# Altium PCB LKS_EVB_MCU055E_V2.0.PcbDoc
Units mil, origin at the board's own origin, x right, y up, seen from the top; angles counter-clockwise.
Board outline 1880 x 1270 mil, 2 copper layers (Top Layer, Bottom Layer); 19 components, 27 nets, 78 pads, 29 vias.
Unrouted connection lines stored in the file: 1.
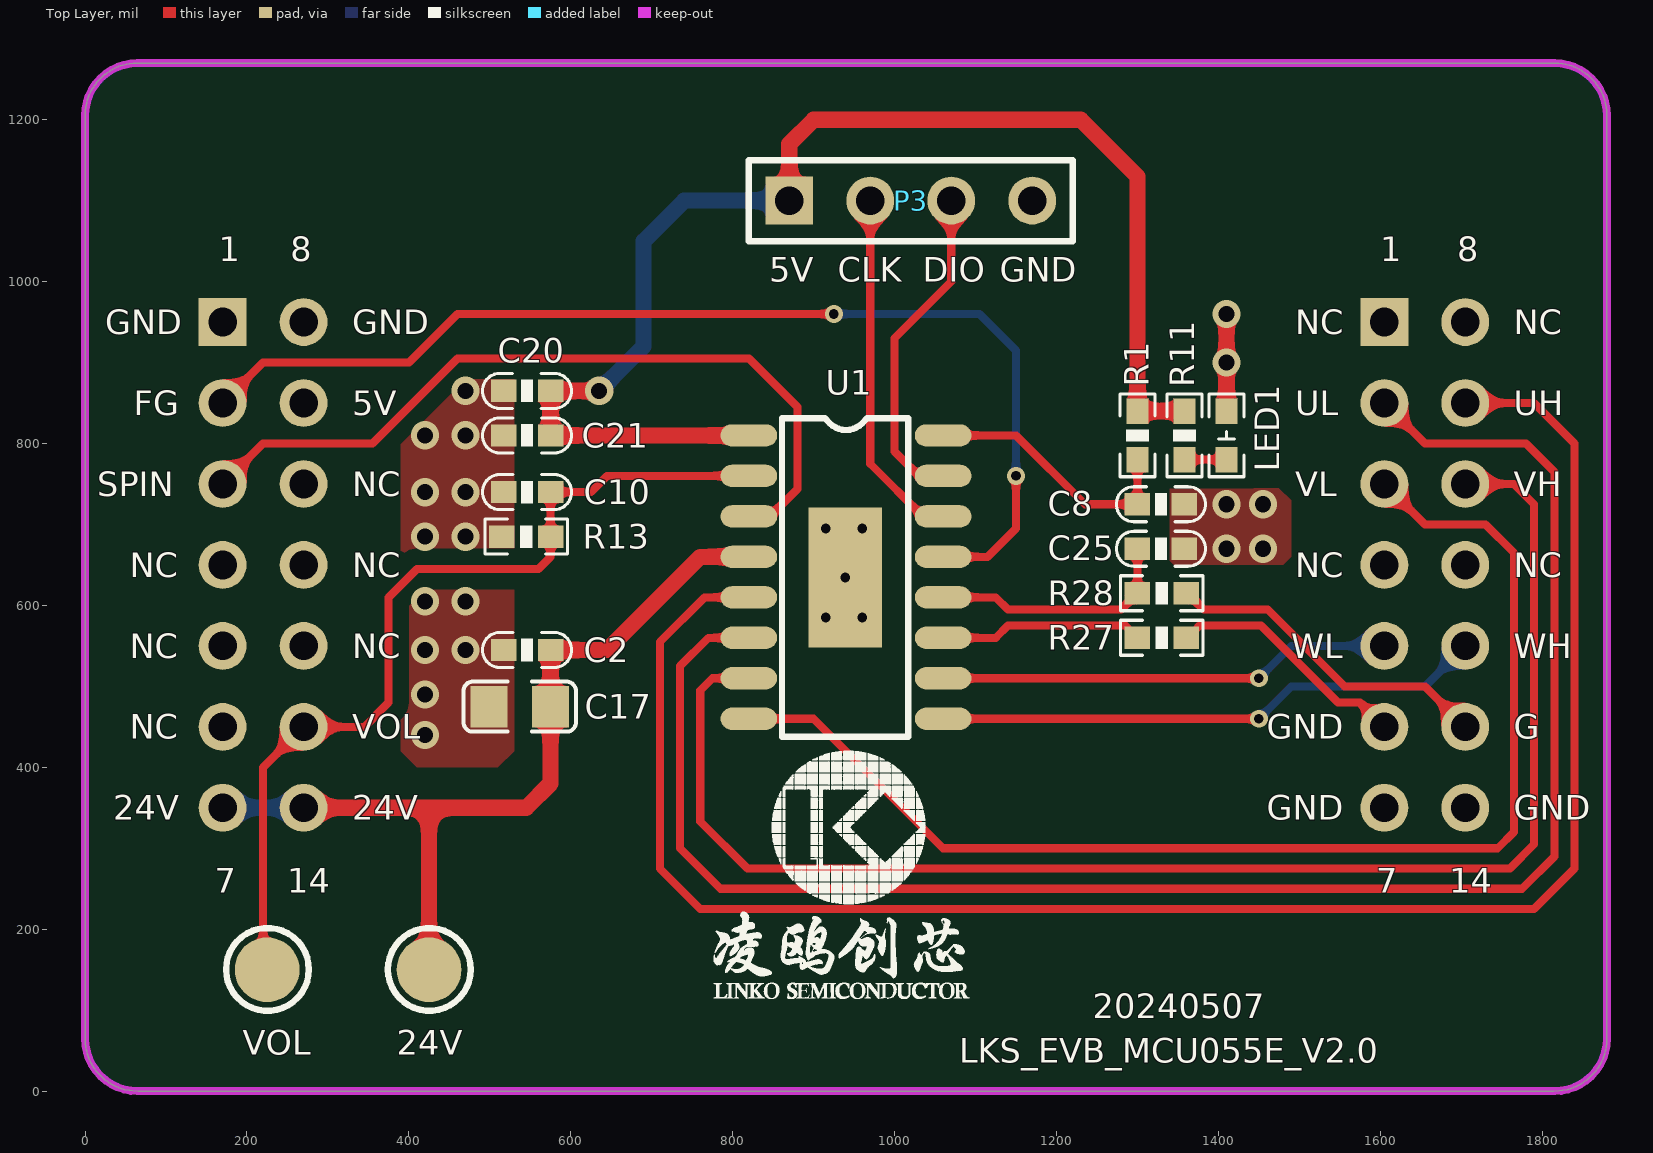
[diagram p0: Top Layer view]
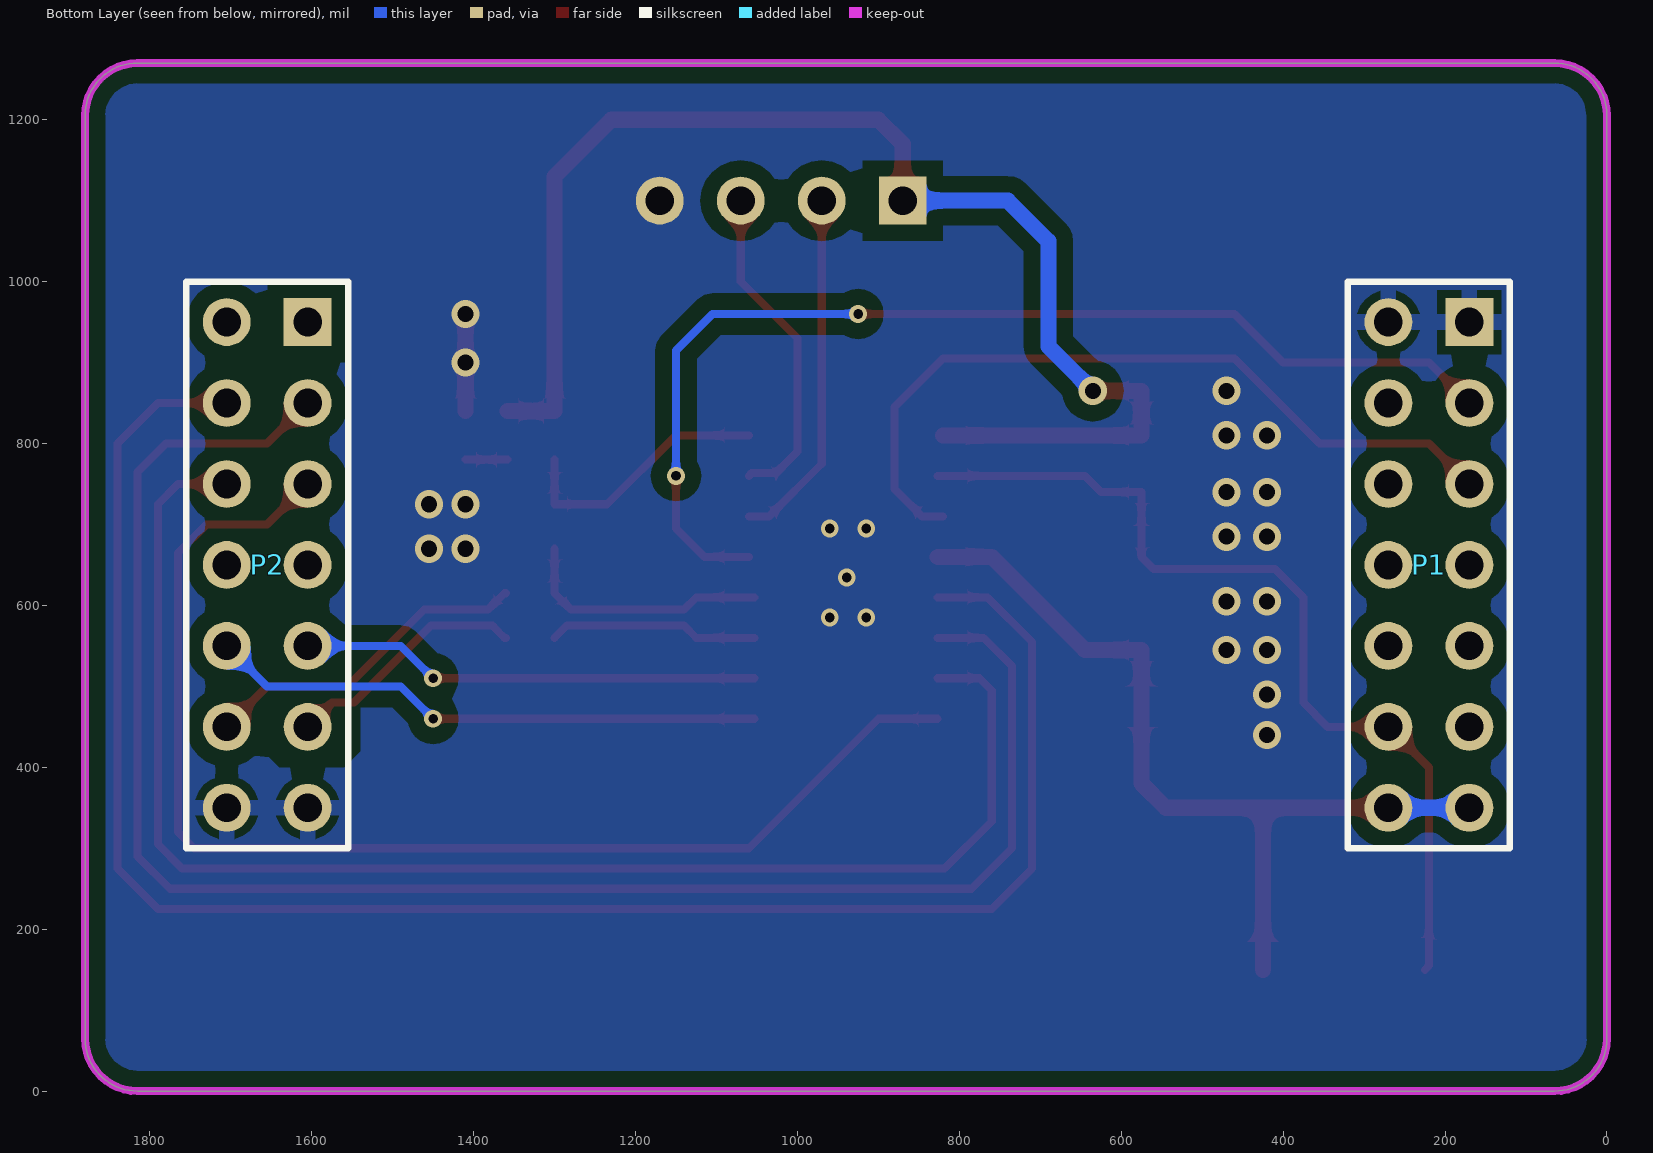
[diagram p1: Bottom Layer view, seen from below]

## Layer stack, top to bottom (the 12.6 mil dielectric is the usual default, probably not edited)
Top Solder: solder mask 0.4, Solder Resist, Dk 3.5
Top Layer: signal copper 1.4
Dielectric1: dielectric 12.6, FR-4, Dk 4.8
Bottom Layer: signal copper 1.4
Bottom Solder: solder mask 0.4, Solder Resist, Dk 3.5

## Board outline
0,65 0,1205 cw(c65,1205) 65,1270 1815,1270 cw(c1815,1205) 1880,1205 1880,65 cw(c1815,65) 1815,0 65,0 cw(c65,65)

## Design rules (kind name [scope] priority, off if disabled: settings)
Clearance Clearance_1 [INPolygon] p1: gap=20 ignorepadtopadclearanceinfootprint=FALSE except(0: Arc-Hole Track-Hole SMDPad-Hole THPad-Hole Via-Hole Fill-Hole Poly-Hole Region-Hole Text-Hole)
Clearance [All] p2: gap=10 ignorepadtopadclearanceinfootprint=FALSE except(0: Arc-Hole Track-Hole SMDPad-Hole THPad-Hole Via-Hole Fill-Hole Poly-Hole Region-Hole Text-Hole)
ComponentClearance [All] p1: gap=0 collisioncheckmode=3 verticalgap=0 showdistances=FALSE
FabricationTestpoint [(IsPad And (OnTopLayer Or OnBottomLayer))] p1: side=3 testpointundercomponent=TRUE minsize=40 maxsize=100 preferedsize=60 minholesize=0 maxholesize=40 preferedholesize=32 testpointgrid=1 allowsidetop=TRUE allowsidebottom=TRUE usegrid=TRUE gridtolerance=0.01
PolygonConnect PolygonConnect_1 [HasFootprint('HDR2X7_CEN') vs InNet('GND')] p1: connectstyle=Relief reliefconductorwidth=20 reliefentries=4 polygonreliefangle="90 Angle" airgapwidth=10
PolygonConnect [All] p2: connectstyle=Direct reliefconductorwidth=20 reliefentries=4 polygonreliefangle="90 Angle" airgapwidth=10
RoutingVias [All] p1: holewidth=12 width=20 viastyle="Through Hole" minholewidth=0 minwidth=10 maxholewidth=30 maxwidth=50
SilkToSolderMaskClearance SilkscreenOverComponentPads [IsPad] p1: minsilkscreentomaskgap=10 clearancetoexposedcopper=TRUE
SolderMaskExpansion [All] p1: expansion=4 istentingtop=FALSE
Width [All] p1: maxlimit=300 minlimit=1 preferedwidth=10
27 further rules are at their usual default settings.

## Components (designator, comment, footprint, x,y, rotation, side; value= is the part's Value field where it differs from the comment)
24V "TestP" TP-80 425.39,150.39 r90 top
C2 "100nF/50V" 0603C 546,545 r180 top
C8 "100nF/50V" 0603C 1329,725 r0 top
C10 "100nF/50V" 0603C 546,740 r180 top
C17 "10uF/50V" 0805C 537,475 r0 top
C20 "10uF/16V" 0603C 545.95,865 r0 top
C21 "100nF/50V" 0603C 546,810 r180 top
C25 "100pF/50V" 0603C 1329.06,670 r180 top
LED1 "" "LED 0603R" 1410,810 r90 top
P1 "Header 7X2A" HDR2X7_CEN 170,950 r270 bottom locked
P2 "Header 7X2A" HDR2X7_CEN 1605,950 r270 bottom locked
P3 "SWD" "HDR 1X4" 870,1100 r0 top
R1 "20K" 0603R 1300,810 r270 top
R11 "3.3K" 0603R 1358.06,810 r90 top
R13 "3.3K" 0603R 545,685 r180 top
R27 "1K" 0603R 1330,560 r0 top
R28 "1K" 0603R 1330,615 r0 top
U1 "LKS32MC055EL6S8" ESOP16 940,635 r0 top locked
VOL "TestP" TP-80 225.39,150.39 r90 top

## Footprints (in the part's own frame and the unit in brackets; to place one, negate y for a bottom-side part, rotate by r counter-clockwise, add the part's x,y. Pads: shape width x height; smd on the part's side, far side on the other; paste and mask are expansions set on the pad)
0603C [mm] "电容"
  rect 0.8x0.7 smd: 1(-0.737,0) 2(0.738,0)
  silkscreen extent -1.4,-0.55 1.4,0.55, body extent -0.8,-0.41 0.8,0.41, height 0.81
0603R [mm] "电阻"
  rect 0.8x0.7 smd: 1(-0.762,0) 2(0.762,0)
  silkscreen extent -1.3,-0.55 1.3,0.55, body extent -0.8,-0.4 0.8,0.4, height 0.45
0805C [mil] "电容"
  rect 46x51.18 smd: 1(-38,0) 2(38,0)
  silkscreen extent -69,-31 70,31, body extent -39,-24 39,24, height 20
ESOP16 [mil]
  round 15.75 on Top Overlay: 0(-48,167)
  rect 90.55x173.23 smd: 0(-1,-0.5)
  oval 70x27.56 smd: 1(-120,175) 2(-120,125) 3(-120,75) 4(-120,25) 5(-120,-25) 6(-120,-75) 7(-120,-125) 8(-120,-175) 9(120,-175) 10(120,-125) 11(120,-75) 12(120,-25) 13(120,25) 14(120,75) 15(120,125) 16(120,175)
  silkscreen extent -79,-197 77,196, body extent -119,-197 117,196, height 75
HDR2X7_CEN [mm] "Connector; Header; 7x2 Position"
  rect 1.5x1.5 hole 0.9: 1(0,0)
  round 1.5 hole 0.9: 2(2.54,0) 3(5.08,0) 4(7.62,0) 5(10.16,0) 6(12.7,0) 7(15.24,0) 8(0,-2.54) 9(2.54,-2.54) 10(5.08,-2.54) 11(7.62,-2.54) 12(10.16,-2.54) 13(12.7,-2.54) 14(15.24,-2.54)
  silkscreen extent -1.27,-3.81 16.51,1.27
"HDR 1X4" [mm] "单排针 2.54mm"
  rect 1.5x1.5 hole 0.9: 1(0,0)
  round 1.5 hole 0.9: 2(2.54,0) 3(5.08,0) 4(7.62,0)
  silkscreen extent -1.27,-1.27 8.89,1.27, body extent -1.27,-1.27 8.89,1.27, height 8.5
"LED 0603R" [mm] "LED"
  rect 0.8x0.7 smd: 1(-0.762,0) 2(0.762,0)
  silkscreen extent -1.3,-0.55 1.3,0.55, body extent -0.8,-0.4 0.8,0.4, height 0.47
TP-80 [mil]
  round 80 smd: 1(-0.39,0.39)
  silkscreen extent -51,-51 51,51

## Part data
C2 C10 C17 C20 C21: library part CAP, "Capacitor"
C8 C25: library part C, "Capacitor"
LED1: library part LED2, "Typical RED, GREEN, YELLOW, AMBER GaAs LED"
P1 P2: "Header, 7-Pin, Dual row"
P3: library part "Header 4", "Header, 4-Pin"
R1 R27 R28: library part RES2-1
R11 R13: library part Res2, "Resistor"
U1: "芯片"

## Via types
v1: diameter 35, hole 20, Top Layer to Bottom Layer, 20 vias
v2: diameter 22, hole 12, Top Layer to Bottom Layer, 9 vias

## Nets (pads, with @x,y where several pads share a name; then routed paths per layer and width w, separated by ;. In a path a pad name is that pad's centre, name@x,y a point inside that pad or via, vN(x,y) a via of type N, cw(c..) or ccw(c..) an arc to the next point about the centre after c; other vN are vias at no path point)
5V: C20.2 C21.1 P3.1 R1.1 R11.2 U1.1 | length 1658
  Top Layer w20: v1(635,865) C20.2 C21.1 U1.1 ; P3.1 870,1170 900,1200 1230,1200 1300,1130 R1.1 R11.2
  Bottom Layer w20: v1(635,865) 690,920 690,1050 740,1100 P3.1
24V: 24V.1 C2.1 C17.2 P1.7 P1.14 U1.4 | length 1081.8
  Top Layer w20: P1.14 425,350 ; 24V.1 425,350 ; U1.4@826.73,660 760,660 645,545 C2.1 C17.2 575,380 545,350 425,350
  Bottom Layer w20: P1.7 P1.14
+5V: P1.9
FG: P1.2 U1.13 | length 1368.7
  Top Layer w10: P1.2 220,900 400,900 460,960 v2(925,960) ; U1.13 1115,660 1150,695 v2(1150,760)
  Bottom Layer w10: v2(925,960) 1105,960 1150,915 v2(1150,760)
G: P2.13 R28.2 | length 413.3
  Top Layer w10: R28.2 1361.97,615 1381.97,595 1461.02,595 1556.02,500 1655,500 P2.13
GND: C2.2 C8.2 C10.2 C17.1 C20.1 C21.2 C25.1 LED1.2 P1.1 P1.8 P2.6 P2.7 P2.14 P3.4 R13.2 R27.2 U1.0@939,634.5 | length 423.2
  Top Layer w10: R27.2 1361.97,560 1370.75,568.78 1370.75,569.14 1376.61,575 1452.74,575 1547.74,480 1575,480 P2.6
  Top Layer w20: LED1.2 v1(1410,900) v1(1410,960)
  other v1: 420,440 420,490 420,545 470,545 420,605 470,605 1410,670 1455,670 420,685 470,685 1410,725 1455,725 420,740 470,740 420,810 470,810 470,865
  other v2: 915,585 960,585 939,634.5 915,695 960,695
HU&PU: P1.10
HV&PV: P1.11
HW&PW: P1.12
NetLED1_1: LED1.1 R11.1 | length 51.9
  Top Layer w10: R11.1 LED1.1
NRST: C8.1 R1.2 U1.16 | length 330.2
  Top Layer w10: U1.16 1150,810 1235,725 C8.1 R1.2
OPA1_IN: R27.1 U1.11 | length 259.2
  Top Layer w10: U1.11@1053.27,560 1125,560 1140,575 1285,575 R27.1
OPA1_IP: C25.2 R28.1 U1.12 | length 316.2
  Top Layer w10: U1.12@1053.27,610 1125,610 1140,595 1280,595 R28.1 C25.2
RXD: P1.6
SPIN: P1.3 U1.3 | length 974.1
  Top Layer w10: P1.3 220,800 355,800 460,905 820,905 880,845 880,744.03 845.97,710 U1.3
SWCLK: P3.2 U1.14 | length 441.9
  Top Layer w10: P3.2 970,775 1035,710 U1.14
SWDIO: P3.3 U1.15 | length 411.4
  Top Layer w10: U1.15 1056.64,763.36 1026.64,763.36 1000,790 1000,930 1070,1000 P3.3
TXD: P1.5
UH: P2.9 U1.5 | length 2271.6
  Top Layer w10: U1.5@826.73,610 765,610 710,555 710,275 760,225 1790,225 1840,275 1840,800 1790,850 P2.9
UL: P2.2 U1.6 | length 2168.7
  Top Layer w10: U1.6@826.73,560 770,560 735,525 735,300 785,250 1775,250 1815,290 1815,765 1780,800 1655,800 P2.2
UX: P2.8
VH: P2.10 U1.7 | length 1816.6
  Top Layer w10: U1.7@826.73,510 775,510 760,495 760,333.28 818.28,275 1760,275 1790,305 1790,725 1765,750 P2.10
VL: P2.3 U1.8 | length 1553
  Top Layer w10: U1.8@826.73,460 900,460 1060,300 1745,300 1765,320 1765,665 1730,700 1655,700 P2.3
VOL: C10.1 P1.13 R13.1 U1.2 VOL.1 | length 1130.9
  Top Layer w10: VOL.1 220,155 220,400 P1.13 345,450 375,480 375,610 410,645 560,645 575,660 C10.1 625,740 645,760 U1.2@826.73,760
VX: P2.11
WH: P2.12 U1.9 | length 689
  Top Layer w10: U1.9@1053.27,460 v2(1450,460)
  Bottom Layer w10: v2(1450,460) 1490,500 1655,500 P2.12
WL: P2.5 U1.10 | length 568.3
  Top Layer w10: U1.10@1053.27,510 v2(1450,510)
  Bottom Layer w10: v2(1450,510) 1490,550 P2.5
pads on no net: P1.4 P2.1 P2.4 U1.0@892,802

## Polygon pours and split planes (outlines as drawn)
GND on Top Layer "10" (solid, remove dead copper, pour order 10): 530,905 390,905 390,420 410,400 510,400 530,420
GND on Top Layer "10" (solid, remove dead copper, pour order 12): 1340,745 1340,655 1345,650 1480,650 1490,660 1490,729.74 1474.74,745
GND on Bottom Layer "Bottom Layer-No Net" (solid, remove dead copper, pour order 4): 0,1270 0,0 1880,0 1880,1270

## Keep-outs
Keep-Out Layer:
  the board outline again, w10

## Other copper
Bottom Layer:
  pour cut-out: 1635,550 1555,550 1540,535 1540,420 1560,400 1640,400 1660,420 1660,525

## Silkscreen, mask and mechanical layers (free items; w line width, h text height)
Top Overlay:
  drawing of 144 lines, arcs and shapes, not listed
  text "5V" at 845,1000 h30
  text "CLK" at 930,1000 h30
  text "DIO" at 1035,1000 h30
  text "GND" at 1130,1000 h30
  text "GND" at 25,935 h30
  text "GND" at 330,935 h30
  text "NC" at 1495,935 h30
  text "NC" at 1765,935 h30
  text "FG" at 60,835 h30
  text "5V" at 330,835 h30
  text "UL" at 1495,835 h30
  text "UH" at 1765,835 h30
  text "SPIN" at 15,735 h30
  text "NC" at 330,735 h30
  text "VL" at 1495,735 h30
  text "VH" at 1765,735 h30
  text "NC" at 55,635 h30
  text "NC" at 330,635 h30
  text "NC" at 1495,635 h30
  text "NC" at 1765,635 h30
  text "NC" at 55,535 h30
  text "NC" at 330,535 h30
  text "WL" at 1490,535 h30
  text "WH" at 1765,535 h30
  text "NC" at 55,435 h30
  text "VOL" at 330,435 h30
  text "GND" at 1460,435 h30
  text "G" at 1765,435 h30
  text "24V" at 35,335 h30
  text "24V" at 330,335 h30
  text "GND" at 1460,335 h30
  text "GND" at 1765,335 h30
  text "20240507" at 1245,90 h30
  text "LKS_EVB_MCU055E_V2.0" at 1080,35 h30
Mechanical 1:
  the board outline again, w10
